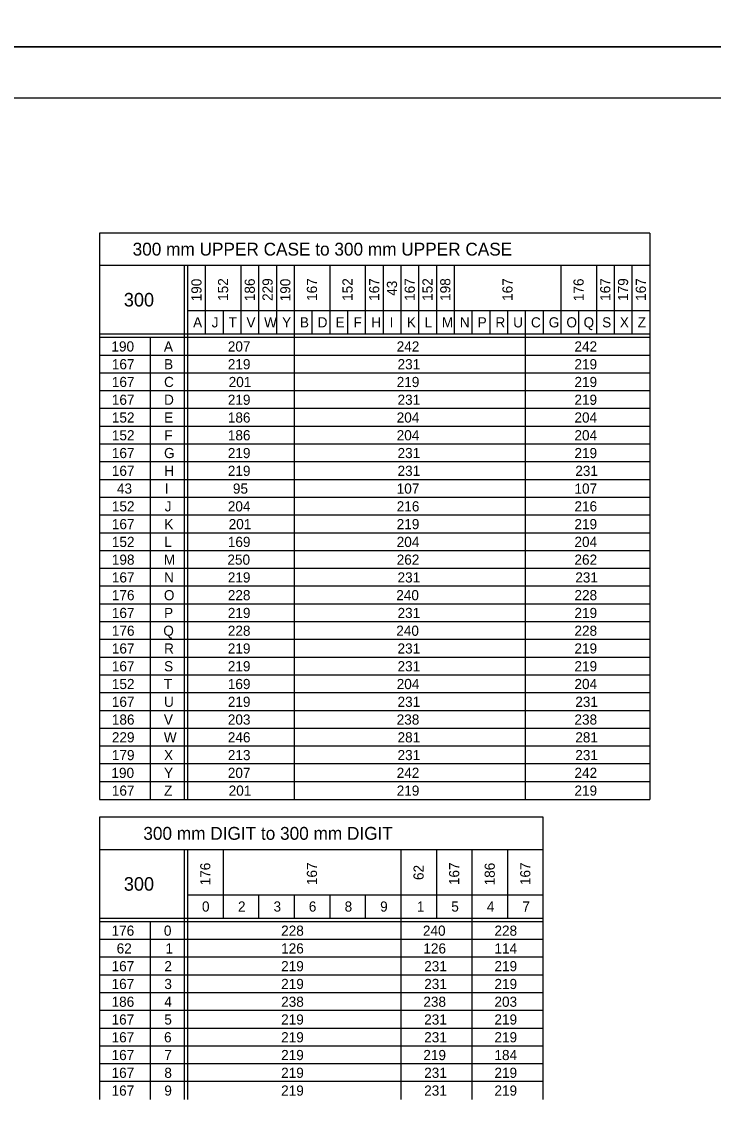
# Model space of a CAD drawing. Extents: x 637580 to 641849, y 297270 to 299646.
# Drawn here: x 638655.2 to 638859.5, y 298740.6 to 299059.1 of the extents above; entities that cross this region are included whole.
import ezdxf

# ---------------------------------------------------------------- set-up
doc = ezdxf.new("R2010")
doc.units = 0
for name, color, linetype in [('1', 7, 'Continuous'), ('2', 7, 'Continuous'), ('XCS-GRID-HVGL', 7, 'Continuous')]:
    doc.layers.add(name, color=color, linetype=linetype)

msp = doc.modelspace()

# ---------------------------------------------------------------- linework, layer by layer
at = {"layer": '1'}
msp.add_line((638461.31, 299036.63), (639247.31, 299036.63), dxfattribs=at)
at = {"layer": '2'}
for p, q in [((638840.71, 298996.63), (638678.21, 298996.63)), ((638678.21, 298996.63), (638678.21, 298829.25)), ((638840.71, 298996.63), (638840.71, 298829.25)), ((638678.21, 298987.13), (638840.71, 298987.13)), ((638703.21, 298987.13), (638703.21, 298829.25)), ((638704.21, 298987.13), (638704.21, 298829.25)), ((638709.46, 298987.13), (638709.46, 298966.75)), ((638719.96, 298987.13), (638719.96, 298966.75)), ((638725.21, 298987.13), (638725.21, 298966.75)), ((638730.46, 298987.13), (638730.46, 298966.75)), ((638735.71, 298987.13), (638735.71, 298829.25)), ((638746.21, 298987.13), (638746.21, 298966.75)), ((638756.71, 298987.13), (638756.71, 298966.75)), ((638761.96, 298987.13), (638761.96, 298966.75)), ((638767.21, 298987.13), (638767.21, 298966.75)), ((638772.46, 298987.13), (638772.46, 298966.75)), ((638777.71, 298987.13), (638777.71, 298966.75)), ((638782.96, 298987.13), (638782.96, 298966.75)), ((638814.46, 298987.13), (638814.46, 298966.75)), ((638824.96, 298987.13), (638824.96, 298966.75)), ((638830.21, 298987.13), (638830.21, 298966.75)), ((638835.46, 298987.13), (638835.46, 298966.75)), ((638704.21, 298973.75), (638840.71, 298973.75)), ((638714.71, 298973.75), (638714.71, 298966.75)), ((638740.96, 298973.75), (638740.96, 298966.75)), ((638751.46, 298973.75), (638751.46, 298966.75)), ((638788.21, 298973.75), (638788.21, 298966.75)), ((638793.46, 298973.75), (638793.46, 298966.75)), ((638798.71, 298973.75), (638798.71, 298966.75)), ((638798.71, 298973.75), (638798.71, 298966.75)), ((638803.96, 298973.75), (638803.96, 298829.25)), ((638809.21, 298973.75), (638809.21, 298966.75)), ((638819.71, 298973.75), (638819.71, 298966.75)), ((638840.71, 298966.75), (638678.21, 298966.75)), ((638840.71, 298965.75), (638678.21, 298965.75)), ((638693.21, 298965.75), (638693.21, 298829.25)), ((638840.71, 298960.5), (638678.21, 298960.5)), ((638840.71, 298955.25), (638678.21, 298955.25)), ((638840.71, 298950), (638678.21, 298950)), ((638840.71, 298944.75), (638678.21, 298944.75)), ((638840.71, 298939.5), (638678.21, 298939.5)), ((638840.71, 298934.25), (638678.21, 298934.25)), ((638840.71, 298929), (638678.21, 298929)), ((638840.71, 298923.75), (638678.21, 298923.75)), ((638840.71, 298918.5), (638678.21, 298918.5)), ((638840.71, 298913.25), (638678.21, 298913.25)), ((638840.71, 298908), (638678.21, 298908)), ((638840.71, 298902.75), (638678.21, 298902.75)), ((638840.71, 298897.5), (638678.21, 298897.5)), ((638840.71, 298892.25), (638678.21, 298892.25)), ((638840.71, 298887), (638678.21, 298887)), ((638840.71, 298881.75), (638678.21, 298881.75)), ((638840.71, 298876.5), (638678.21, 298876.5)), ((638840.71, 298871.25), (638678.21, 298871.25)), ((638840.71, 298866), (638678.21, 298866)), ((638840.71, 298860.75), (638678.21, 298860.75)), ((638840.71, 298855.5), (638678.21, 298855.5)), ((638840.71, 298850.25), (638678.21, 298850.25)), ((638840.71, 298845), (638678.21, 298845)), ((638840.71, 298839.75), (638678.21, 298839.75)), ((638840.71, 298834.5), (638678.21, 298834.5)), ((638678.21, 298829.25), (638678.21, 298829.25)), ((638678.21, 298829.25), (638840.71, 298829.25)), ((638809.21, 298824), (638678.21, 298824)), ((638678.21, 298824), (638678.21, 298740.63)), ((638809.21, 298740.63), (638809.21, 298824)), ((638678.21, 298814.5), (638809.21, 298814.5)), ((638703.21, 298814.5), (638703.21, 298740.63)), ((638704.21, 298814.5), (638704.21, 298740.63)), ((638714.71, 298814.5), (638714.71, 298794.13)), ((638767.21, 298814.5), (638767.21, 298740.63)), ((638777.71, 298814.5), (638777.71, 298794.13)), ((638788.21, 298814.5), (638788.21, 298740.63)), ((638798.71, 298814.5), (638798.71, 298794.13)), ((638704.21, 298801.13), (638809.21, 298801.13)), ((638725.21, 298801.13), (638725.21, 298794.13)), ((638735.71, 298801.13), (638735.71, 298794.13)), ((638746.21, 298801.13), (638746.21, 298794.13)), ((638756.71, 298801.13), (638756.71, 298794.13)), ((638809.21, 298794.13), (638678.21, 298794.13)), ((638809.21, 298793.13), (638678.21, 298793.13)), ((638693.21, 298793.13), (638693.21, 298740.63)), ((638809.21, 298787.88), (638678.21, 298787.88)), ((638809.21, 298782.63), (638678.21, 298782.63)), ((638809.21, 298777.38), (638678.21, 298777.38)), ((638809.21, 298772.13), (638678.21, 298772.13)), ((638809.21, 298766.88), (638678.21, 298766.88)), ((638809.21, 298761.63), (638678.21, 298761.63)), ((638809.21, 298756.38), (638678.21, 298756.38)), ((638809.21, 298751.13), (638678.21, 298751.13)), ((638809.21, 298745.88), (638678.21, 298745.88))]:
    msp.add_line(p, q, dxfattribs=at)
at = {"layer": 'XCS-GRID-HVGL'}
for points in [[(638421.31, 299645.63), (639262.31, 299645.63), (639262.31, 299051.63), (638421.31, 299051.63)], [(638421.31, 299051.63), (639262.31, 299051.63), (639262.31, 298457.63), (638421.31, 298457.63)]]:
    msp.add_lwpolyline(points, close=True, dxfattribs=at)

# ---------------------------------------------------------------- texts
at = {"layer": '2'}
for s, height, p in [('300 mm UPPER CASE to 300 mm UPPER CASE', 3.8, (638688, 298989.98)), ('300', 4, (638685.4, 298974.94)), ('A', 3, (638705.86, 298968.75)), ('J', 3, (638711.34, 298968.75)), ('T', 3, (638716.34, 298968.75)), ('V', 3, (638721.61, 298968.75)), ('W', 3, (638726.83, 298968.75)), ('Y', 3, (638732.14, 298968.75)), ('B', 3, (638737.4, 298968.75)), ('D', 3, (638742.65, 298968.75)), ('E', 3, (638747.92, 298968.75)), ('F', 3, (638753.22, 298968.75)), ('H', 3, (638758.49, 298968.75)), ('I', 3, (638763.9, 298968.75)), ('K', 3, (638768.99, 298968.75)), ('L', 3, (638774.24, 298968.75)), ('M', 3, (638779.33, 298968.75)), ('N', 3, (638784.65, 298968.75)), ('P', 3, (638789.9, 298968.75)), ('R', 3, (638795.15, 298968.75)), ('U', 3, (638800.39, 298968.75)), ('C', 3, (638805.65, 298968.75)), ('G', 3, (638810.9, 298968.75)), ('O', 3, (638816.11, 298968.75)), ('Q', 3, (638821.18, 298968.75)), ('S', 3, (638826.67, 298968.75)), ('X', 3, (638831.89, 298968.75)), ('Z', 3, (638837.15, 298968.75)), ('190', 3, (638681.73, 298961.63)), ('A', 3, (638697.23, 298961.63)), ('207', 3, (638716.11, 298961.63)), ('242', 3, (638765.99, 298961.63)), ('242', 3, (638818.49, 298961.63)), ('167', 3, (638681.86, 298956.38)), ('B', 3, (638697.28, 298956.38)), ('219', 3, (638716.11, 298956.38)), ('231', 3, (638766.24, 298956.38)), ('219', 3, (638818.49, 298956.38)), ('167', 3, (638681.86, 298951.13)), ('C', 3, (638697.28, 298951.13)), ('201', 3, (638716.36, 298951.13)), ('219', 3, (638765.99, 298951.13)), ('219', 3, (638818.49, 298951.13)), ('167', 3, (638681.86, 298945.88)), ('D', 3, (638697.28, 298945.88)), ('219', 3, (638716.11, 298945.88)), ('231', 3, (638766.24, 298945.88)), ('219', 3, (638818.49, 298945.88)), ('152', 3, (638681.86, 298940.63)), ('E', 3, (638697.29, 298940.63)), ('186', 3, (638716.11, 298940.63)), ('204', 3, (638765.99, 298940.63)), ('204', 3, (638818.49, 298940.63)), ('152', 3, (638681.86, 298935.38)), ('F', 3, (638697.35, 298935.38)), ('186', 3, (638716.11, 298935.38)), ('204', 3, (638765.99, 298935.38)), ('204', 3, (638818.49, 298935.38)), ('167', 3, (638681.86, 298930.13)), ('G', 3, (638697.28, 298930.13)), ('219', 3, (638716.11, 298930.13)), ('231', 3, (638766.24, 298930.13)), ('219', 3, (638818.49, 298930.13)), ('167', 3, (638681.86, 298924.88)), ('H', 3, (638697.36, 298924.88)), ('219', 3, (638716.11, 298924.88)), ('231', 3, (638766.24, 298924.88)), ('231', 3, (638818.74, 298924.88)), ('43', 3, (638683.36, 298919.63)), ('I', 3, (638697.53, 298919.63)), ('95', 3, (638717.61, 298919.63)), ('107', 3, (638765.99, 298919.63)), ('107', 3, (638818.49, 298919.63)), ('152', 3, (638681.86, 298914.38)), ('J', 3, (638697.47, 298914.38)), ('204', 3, (638716.11, 298914.38)), ('216', 3, (638765.99, 298914.38)), ('216', 3, (638818.49, 298914.38)), ('167', 3, (638681.86, 298909.13)), ('K', 3, (638697.36, 298909.13)), ('201', 3, (638716.36, 298909.13)), ('219', 3, (638765.99, 298909.13)), ('219', 3, (638818.49, 298909.13)), ('152', 3, (638681.86, 298903.88)), ('L', 3, (638697.36, 298903.88)), ('169', 3, (638716.11, 298903.88)), ('204', 3, (638765.99, 298903.88)), ('204', 3, (638818.49, 298903.88)), ('198', 3, (638681.86, 298898.63)), ('M', 3, (638697.21, 298898.63)), ('250', 3, (638715.99, 298898.63)), ('262', 3, (638765.99, 298898.63)), ('262', 3, (638818.49, 298898.63)), ('167', 3, (638681.86, 298893.38)), ('219', 3, (638716.11, 298893.38)), ('231', 3, (638766.24, 298893.38)), ('231', 3, (638818.74, 298893.38)), ('N', 3, (638697.28, 298893.38)), ('176', 3, (638681.86, 298888.13)), ('O', 3, (638697.23, 298888.13)), ('228', 3, (638716.11, 298888.13)), ('240', 3, (638765.86, 298888.13)), ('228', 3, (638818.49, 298888.13)), ('167', 3, (638681.86, 298882.88)), ('P', 3, (638697.28, 298882.88)), ('219', 3, (638716.11, 298882.88)), ('231', 3, (638766.24, 298882.88)), ('219', 3, (638818.49, 298882.88)), ('176', 3, (638681.86, 298877.63)), ('Q', 3, (638697.05, 298877.63)), ('228', 3, (638716.11, 298877.63)), ('240', 3, (638765.86, 298877.63)), ('228', 3, (638818.49, 298877.63)), ('167', 3, (638681.86, 298872.38)), ('R', 3, (638697.28, 298872.38)), ('219', 3, (638716.11, 298872.38)), ('231', 3, (638766.24, 298872.38)), ('219', 3, (638818.49, 298872.38)), ('167', 3, (638681.86, 298867.13)), ('S', 3, (638697.29, 298867.13)), ('219', 3, (638716.11, 298867.13)), ('231', 3, (638766.24, 298867.13)), ('219', 3, (638818.49, 298867.13)), ('152', 3, (638681.86, 298861.88)), ('T', 3, (638697.22, 298861.88)), ('169', 3, (638716.11, 298861.88)), ('204', 3, (638765.99, 298861.88)), ('204', 3, (638818.49, 298861.88)), ('167', 3, (638681.86, 298856.63)), ('U', 3, (638697.27, 298856.63)), ('219', 3, (638716.11, 298856.63)), ('231', 3, (638766.24, 298856.63)), ('231', 3, (638818.74, 298856.63)), ('186', 3, (638681.86, 298851.38)), ('V', 3, (638697.23, 298851.38)), ('203', 3, (638716.11, 298851.38)), ('238', 3, (638765.99, 298851.38)), ('238', 3, (638818.49, 298851.38)), ('229', 3, (638681.86, 298846.13)), ('W', 3, (638697.21, 298846.13)), ('246', 3, (638716.11, 298846.13)), ('281', 3, (638766.24, 298846.13)), ('281', 3, (638818.74, 298846.13)), ('179', 3, (638681.86, 298840.88)), ('X', 3, (638697.27, 298840.88)), ('213', 3, (638716.11, 298840.88)), ('231', 3, (638766.24, 298840.88)), ('231', 3, (638818.74, 298840.88)), ('190', 3, (638681.73, 298835.63)), ('Y', 3, (638697.27, 298835.63)), ('207', 3, (638716.11, 298835.63)), ('242', 3, (638765.99, 298835.63)), ('242', 3, (638818.49, 298835.63)), ('167', 3, (638681.86, 298830.38)), ('Z', 3, (638697.28, 298830.38)), ('201', 3, (638716.36, 298830.38)), ('219', 3, (638765.99, 298830.38)), ('219', 3, (638818.49, 298830.38)), ('300 mm DIGIT to 300 mm DIGIT', 3.8, (638691.16, 298817.35)), ('300', 4, (638685.4, 298802.31)), ('0', 3, (638708.48, 298796.13)), ('2', 3, (638719.11, 298796.13)), ('3', 3, (638729.61, 298796.13)), ('6', 3, (638740.03, 298796.13)), ('8', 3, (638750.61, 298796.13)), ('9', 3, (638761.1, 298796.13)), ('1', 3, (638771.95, 298796.13)), ('5', 3, (638782.11, 298796.13)), ('4', 3, (638792.61, 298796.13)), ('7', 3, (638803.11, 298796.13)), ('176', 3, (638681.78, 298789)), ('0', 3, (638697.23, 298789)), ('228', 3, (638731.86, 298789)), ('240', 3, (638773.73, 298789)), ('228', 3, (638794.86, 298789)), ('62', 3, (638683.28, 298783.75)), ('1', 3, (638697.7, 298783.75)), ('126', 3, (638731.86, 298783.75)), ('126', 3, (638773.86, 298783.75)), ('114', 3, (638794.86, 298783.75)), ('167', 3, (638681.78, 298778.5)), ('2', 3, (638697.36, 298778.5)), ('219', 3, (638731.86, 298778.5)), ('231', 3, (638774.11, 298778.5)), ('219', 3, (638794.86, 298778.5)), ('167', 3, (638681.78, 298773.25)), ('3', 3, (638697.36, 298773.25)), ('219', 3, (638731.86, 298773.25)), ('231', 3, (638774.11, 298773.25)), ('219', 3, (638794.86, 298773.25)), ('186', 3, (638681.78, 298768)), ('4', 3, (638697.36, 298768)), ('238', 3, (638731.86, 298768)), ('238', 3, (638773.86, 298768)), ('203', 3, (638794.86, 298768)), ('167', 3, (638681.78, 298762.75)), ('5', 3, (638697.36, 298762.75)), ('219', 3, (638731.86, 298762.75)), ('231', 3, (638774.11, 298762.75)), ('219', 3, (638794.86, 298762.75)), ('167', 3, (638681.78, 298757.5)), ('6', 3, (638697.28, 298757.5)), ('219', 3, (638731.86, 298757.5)), ('231', 3, (638774.11, 298757.5)), ('219', 3, (638794.86, 298757.5)), ('167', 3, (638681.78, 298752.25)), ('7', 3, (638697.36, 298752.25)), ('219', 3, (638731.86, 298752.25)), ('219', 3, (638773.86, 298752.25)), ('184', 3, (638794.86, 298752.25)), ('167', 3, (638681.78, 298747)), ('8', 3, (638697.36, 298747)), ('219', 3, (638731.86, 298747)), ('231', 3, (638774.11, 298747)), ('219', 3, (638794.86, 298747)), ('167', 3, (638681.78, 298741.75)), ('9', 3, (638697.35, 298741.75)), ('219', 3, (638731.86, 298741.75)), ('231', 3, (638774.11, 298741.75)), ('219', 3, (638794.86, 298741.75))]:
    msp.add_text(s, height=height, dxfattribs=at).set_placement(p)
for s, p in [('190', (638708.34, 298976.46)), ('152', (638716.21, 298976.59)), ('186', (638724.09, 298976.51)), ('229', (638729.34, 298976.58)), ('190', (638734.59, 298976.46)), ('167', (638742.46, 298976.59)), ('152', (638752.96, 298976.59)), ('167', (638760.84, 298976.59)), ('167', (638771.34, 298976.59)), ('152', (638776.59, 298976.59)), ('198', (638781.84, 298976.59)), ('167', (638800.21, 298976.59)), ('176', (638821.21, 298976.51)), ('167', (638829.09, 298976.59)), ('179', (638834.34, 298976.58)), ('167', (638839.59, 298976.59)), ('43', (638766.09, 298978.09)), ('176', (638710.96, 298803.88)), ('167', (638742.46, 298803.96)), ('167', (638784.46, 298803.96)), ('186', (638794.96, 298803.88)), ('167', (638805.46, 298803.96)), ('62', (638773.96, 298805.46))]:
    msp.add_text(s, height=3, rotation=90, dxfattribs=at).set_placement(p)

doc.saveas('drawing.dxf')
